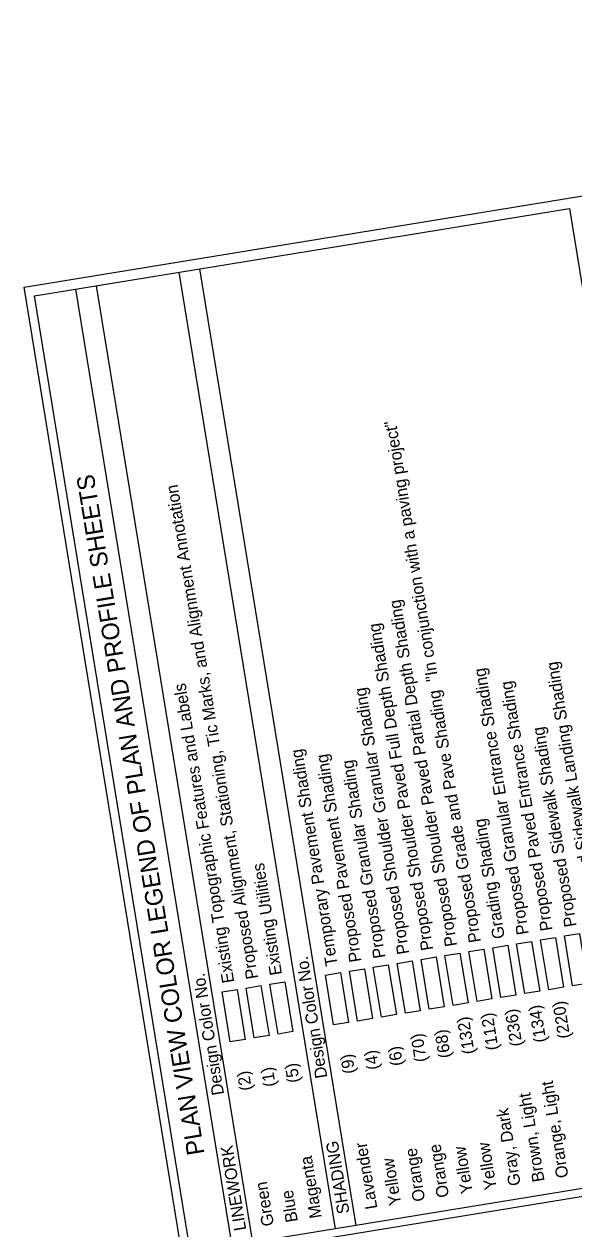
# Model space of a CAD drawing. Extents: x 21481360 to 21488265, y 8074918 to 8087833.
# Drawn here: x 21481360 to 21482042, y 8086342 to 8087833 of the extents above; entities that cross this region are included whole.
import ezdxf

# ---------------------------------------------------------------- set-up
doc = ezdxf.new("R2010")
doc.units = 0
for name, color, linetype in [('Default', 7, 'Continuous'), ('EXT_DU', 7, 'Continuous'), ('EXT_EP', 7, 'Continuous'), ('EXT_SH', 7, 'Continuous'), ('NamedBoundary', 7, 'Continuous'), ('Roadways', 7, 'Continuous'), ('Section Lines', 7, 'Continuous'), ('SurControl', 7, 'Continuous'), ('Text', 7, 'Continuous'), ('TextAlignment', 7, 'Continuous'), ('Wall', 7, 'Continuous')]:
    doc.layers.add(name, color=color, linetype=linetype)

msp = doc.modelspace()

# ---------------------------------------------------------------- linework, layer by layer
at = {"layer": 'Default'}
msp.add_lwpolyline([(21481866.1, 8084413.6), (21481360.5, 8087507.5), (21483354, 8087833.3), (21483859.7, 8084739.4)], close=True, dxfattribs=at)
at = {"layer": 'EXT_DU'}
msp.add_lwpolyline([(21481951.3, 8086628.3), (21481941.2, 8086689.9), (21481959.7, 8086693), (21481969.8, 8086631.3)], close=True, dxfattribs=at)
at = {"layer": 'EXT_EP'}
msp.add_lwpolyline([(21481675.2, 8086583.1), (21481665.1, 8086644.8), (21481683.6, 8086647.9), (21481693.7, 8086586.2)], close=True, dxfattribs=at)
at = {"layer": 'NamedBoundary'}
msp.add_lwpolyline([(21481744, 8086594.4), (21481734, 8086656.1), (21481752.5, 8086659.1), (21481762.6, 8086597.4)], close=True, dxfattribs=at)
at = {"layer": 'Roadways'}
for p, q in [((21481746.3, 8086341.9), (21481552.8, 8087526.2)), ((21481772, 8086346.1), (21481578.4, 8087530.4)), ((21481618.3, 8086320.9), (21481424.7, 8087505.2)), ((21481643.9, 8086325.1), (21481450.4, 8087509.4))]:
    msp.add_line(p, q, dxfattribs=at)
at = {"layer": 'Section Lines'}
msp.add_lwpolyline([(21481645.6, 8086578.3), (21481635.5, 8086640), (21481654, 8086643), (21481664.1, 8086581.3)], close=True, dxfattribs=at)
at = {"layer": 'SurControl'}
msp.add_lwpolyline([(21481566.9, 8086312.6), (21481373.4, 8087496.9), (21482036.1, 8087605.2), (21482229.7, 8086420.9)], close=True, dxfattribs=at)
msp.add_lwpolyline([(21481678.4, 8085630.3), (21481568.4, 8086303.3), (21483540.3, 8086625.6), (21483650.3, 8085952.6), (21481678.4, 8085630.3)], dxfattribs=at)
at = {"layer": 'Text'}
msp.add_lwpolyline([(21481616, 8086573.5), (21481605.9, 8086635.2), (21481624.4, 8086638.2), (21481634.5, 8086576.5)], close=True, dxfattribs=at)
at = {"layer": 'TextAlignment'}
for points in [[(21481980.9, 8086633.1), (21481970.8, 8086694.8), (21481989.3, 8086697.8), (21481999.4, 8086636.1)], [(21482010.5, 8086637.9), (21482000.4, 8086699.6), (21482018.9, 8086702.7), (21482029, 8086641)], [(21481892.1, 8086618.6), (21481882, 8086680.3), (21481900.5, 8086683.3), (21481910.6, 8086621.6)], [(21481803.3, 8086604.1), (21481793.2, 8086665.8), (21481811.7, 8086668.8), (21481821.8, 8086607.1)], [(21481832.9, 8086608.9), (21481822.8, 8086670.6), (21481841.3, 8086673.6), (21481851.4, 8086611.9)], [(21481862.5, 8086613.8), (21481852.4, 8086675.4), (21481870.9, 8086678.5), (21481881, 8086616.8)], [(21481773.7, 8086599.2), (21481763.6, 8086660.9), (21481782.1, 8086663.9), (21481792.2, 8086602.3)]]:
    msp.add_lwpolyline(points, close=True, dxfattribs=at)
at = {"layer": 'Wall'}
for points in [[(21482040.1, 8086642.8), (21482030, 8086704.5), (21482048.5, 8086707.5), (21482058.6, 8086645.8)], [(21481921.7, 8086623.4), (21481911.6, 8086685.1), (21481930.1, 8086688.1), (21481940.2, 8086626.5)]]:
    msp.add_lwpolyline(points, close=True, dxfattribs=at)

# ---------------------------------------------------------------- texts
at = {"layer": 'EXT_SH'}
for s, height, p in [('Proposed Grade and Pave Shading  "In conjunction with a paving project"', 15, (21481926.7, 8086697.4)), ('PLAN VIEW COLOR LEGEND OF PLAN AND PROFILE SHEETS', 21.667, (21481584.2, 8086435)), ('Proposed Alignment, Stationing, Tic Marks, and Alignment Annotation ', 15, (21481650.6, 8086652.3)), ('Proposed Shoulder Paved Partial Depth Shading', 15, (21481897.1, 8086692.6)), ('Proposed Shoulder Paved Full Depth Shading', 15, (21481867.5, 8086687.7)), ('Proposed Sidewalk Landing Shading', 15, (21482074.7, 8086721.6)), ('Proposed Granular Entrance Shading', 15, (21481985.9, 8086707.1)), ('Existing Topographic Features and Labels', 15, (21481621, 8086647.4)), ('Proposed Shoulder Granular Shading', 15, (21481837.9, 8086682.9)), ('Proposed Paved Entrance Shading', 15, (21482015.5, 8086711.9)), ('Proposed Sidewalk Shading', 15, (21482045.1, 8086716.8)), ('Temporary Pavement Shading', 15, (21481749.1, 8086668.4)), ('Proposed Pavement Shading', 15, (21481778.7, 8086673.2)), ('Proposed Granular Shading', 15, (21481808.3, 8086678)), ('Grading Shading', 15, (21481956.3, 8086702.2)), ('Existing Utilities ', 15, (21481680.2, 8086657.1)), ('Design Color No.', 15, (21481736.4, 8086529.5)), ('Design Color No.', 15, (21481608.4, 8086508.6)), ('(220) ', 15, (21482037.3, 8086578.7)), ('(112) ', 15, (21481948.5, 8086564.2)), ('(236) ', 15, (21481978.1, 8086569)), ('(134) ', 15, (21482007.7, 8086573.8)), ('(132) ', 15, (21481918.9, 8086559.3)), ('(70) ', 15, (21481859.7, 8086549.6)), ('(68) ', 15, (21481889.3, 8086554.5)), ('(4) ', 15, (21481800.5, 8086540)), ('(6) ', 15, (21481830.1, 8086544.8)), ('(9) ', 15, (21481770.8, 8086535.1)), ('(2) ', 15, (21481642.8, 8086514.2)), ('(1) ', 15, (21481672.4, 8086519)), ('(5) ', 15, (21481702, 8086523.9)), ('Orange, Light', 15, (21482035.1, 8086406.1)), ('Brown, Light', 15, (21482005.5, 8086401.2)), ('Gray, Dark', 15, (21481975.9, 8086396.4)), ('LINEWORK', 15, (21481635.8, 8086340.8)), ('SHADING', 15, (21481763.8, 8086361.7)), ('Lavender', 15, (21481798.3, 8086367.4)), ('Orange', 15, (21481887.1, 8086381.9)), ('Yellow', 15, (21481916.7, 8086386.7)), ('Yellow', 15, (21481946.3, 8086391.6)), ('Magenta', 15, (21481729.4, 8086356.1)), ('Yellow', 15, (21481827.9, 8086372.2)), ('Orange', 15, (21481857.5, 8086377)), ('Green', 15, (21481670.2, 8086346.4)), ('Blue ', 15, (21481699.8, 8086351.3))]:
    msp.add_text(s, height=height, rotation=99.2819, dxfattribs=at).set_placement(p)

doc.saveas('drawing.dxf')
